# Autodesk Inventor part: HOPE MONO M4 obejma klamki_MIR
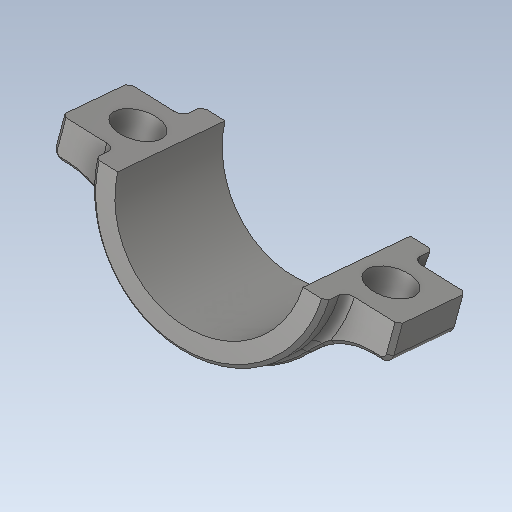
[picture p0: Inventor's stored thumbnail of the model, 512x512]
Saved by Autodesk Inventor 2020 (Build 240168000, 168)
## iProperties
Created: 2015-11
Part Number: HOPE MONO M4 obejma klamki_MIR
Material: Ogólny
Document SubType Name: Modeling
Designer: Tomasz
Density: 1 g/cm^3
Appearance: Domyślna
Sending System: SolidWorks 2017
Last Author: Tomasz
Last Saved: 2017-10-01
Author: Tomasz
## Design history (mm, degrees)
feature "Imported1"
node "Bryła1"
